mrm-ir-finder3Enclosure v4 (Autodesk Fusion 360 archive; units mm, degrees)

design "mrm-ir-finder3Enclosure" references "mrm-ir-finder3"
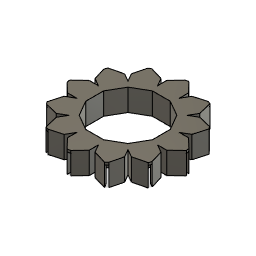
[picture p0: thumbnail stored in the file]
component_insert "Component Insert" AlongDistance 1.5 TaperAngle 0 TranslateX 0 TranslateY 0.5 TranslateZ 0 DistanceX 5.1838 DistanceY 5.3824 DistanceZ -1.6 OffsetDistanceX 0 OffsetDistanceY 0 countU 12 TotalAngle 360 AlongDistance 1.5 TaperAngle 0 TranslateX 0 TranslateY -0.5 TranslateZ 0 DistanceX 7.2 DistanceY 5.3 DistanceZ -1.5 OffsetDistanceX 0 OffsetDistanceY 0 TotalAngle 360 distance -0.2 distance -0.2 DistanceX 4.2933 DistanceY 6.2 DistanceZ -1.5 OffsetDistanceX 0 OffsetDistanceY 0 AlongDistance 0.5 TaperAngle 0 AlongDistance 0.5 TaperAngle 0 AlongDistance 0.5 TaperAngle 0 countU 12 TotalAngle 360 AlongDistance -0.5 TaperAngle 0 distance -0.2 AlongDistance -0.5 TaperAngle 0 AlongDistance -0.5 TaperAngle 0 AlongDistance -0.5 TaperAngle 0 AlongDistance -0.5 TaperAngle 0 AlongDistance -0.5 TaperAngle 0 AlongDistance -0.5 TaperAngle 0 DistanceX 1.5893 DistanceY 9.4 DistanceZ -0.4 OffsetDistanceX 0 OffsetDistanceY 0 AlongDistance -0.5 TaperAngle 0 AlongDistance -0.5 TaperAngle 0 AlongDistance -0.5 TaperAngle 0 AlongDistance -0.5 TaperAngle 0 AlongDistance -0.5 TaperAngle 0 AlongDistance -0.5 TaperAngle 0 AlongDistance -0.5 TaperAngle 0 AlongDistance -0.5 TaperAngle 0
sketch "Sketch8" plane through (0, 29.6609, 0) normal (0, 1, 0) x axis (-1, 0, 0)
  line L1 (-5.3393, 2.2304) -> (-2.6607, 2.2304)
  line L2 (-5.3393, -2.2518) -> (-5.3393, 2.2304)
  line L3 (-2.6607, -2.2518) -> (-5.3393, -2.2518)
  line L4 (-2.6607, 2.2304) -> (-2.6607, -2.2518)
  line L5 (-5.3411, 2.4304) -> (-2.6589, 2.4304)
  line L6 (-5.3393, -2.2518) -> (-2.6607, -2.2518)
  line L7 (-2.6589, -2.4518) -> (-5.3411, -2.4518)
  line L8 (-2.6, 1.9893) -> (-2.6, -2.0107)
  line L9 (-2.6607, 2.2304) -> (-5.3393, 2.2304)
  line L10 (-5.3411, 2.4304) -> (-2.6589, 2.4304)
  line L11 (-2.6589, 2.4304) -> (-5.3411, 2.4304)
  line L12 (-2.6589, -2.4518) -> (-2.6589, 2.4304)
  line L13 (-5.3411, -2.4518) -> (-2.6589, -2.4518)
  line L14 (-5.3411, 2.4304) -> (-5.3411, -2.4518)
  line L15 (-6.3411, -3.4518) -> (-1.6589, -3.4518)
  line L16 (-6.3411, 3.4304) -> (-6.3411, -3.4518)
  line L17 (-1.6589, 3.4304) -> (-6.3411, 3.4304)
  line L18 (-1.6589, -3.4518) -> (-1.6589, 3.4304)
  line L19 (-7.3411, -4.4518) -> (-0.6589, -4.4518)
  line L20 (-7.3411, 4.4304) -> (-7.3411, -4.4518)
  line L21 (-0.6589, 4.4304) -> (-7.3411, 4.4304)
  line L22 (-0.6589, -4.4518) -> (-0.6589, 4.4304)
  line L23 (-6.3411, 3.4304) -> (-1.6589, 3.4304)
  line L24 (-6.3411, 3.4304) -> (-6.3411, -3.4518)
  line L25 (-1.6589, -3.4518) -> (-6.3411, -3.4518)
  line L26 (-1.6589, -3.4518) -> (-1.6589, -2.9518)
  line L27 (-1.6589, 2.9304) -> (-1.6589, 3.4304)
  line L28 (-0.6589, 2.9304) -> (-1.6589, 2.9304)
  line L29 (-0.6589, 4.4304) -> (-0.6589, 2.9304)
  line L30 (-7.3411, 4.4304) -> (-0.6589, 4.4304)
  line L31 (-7.3411, -4.4518) -> (-7.3411, 4.4304)
  line L32 (-0.6589, -4.4518) -> (-7.3411, -4.4518)
  line L33 (-0.6589, -4.4518) -> (-0.6589, -2.9518)
  line L34 (-1.6589, -2.9518) -> (-0.6589, -2.9518)
  line L35 (2.1576, -0.0107) -> (-0.6589, 2.9304)
  line L36 (-0.6589, -2.9518) -> (2.1576, -0.0107)
  line L37 (3.9785, -0.0107) -> (-0.6589, 4.4304)
  line L38 (-0.6589, -4.4518) -> (3.9785, -0.0107)
  line L39 (-0.1379, 0.7317) -> (3, 0.7317)
  line L40 (-0.1379, -0.5) -> (3, -0.5)
  line L41 (3.2033, 0.7317) -> (-0.6589, 4.4304)
  line L42 (3.2033, 0.7317) -> (-0.6589, 4.4304)
  line L43 (1.4467, 0.7317) -> (3.2033, 0.7317)
  line L44 (-0.6589, 2.9304) -> (1.4467, 0.7317)
  line L45 (1.6891, -0.5) -> (-0.6589, -2.9518)
  line L46 (3.4676, -0.5) -> (1.6891, -0.5)
  line L47 (-0.6589, -4.4518) -> (3.4676, -0.5)
  closed curve K1 centre (-2.6589, -2.2518)
  closed curve K2 centre (-5.3411, -2.2518)
  arc A1 centre (-2.6, -0.0107) radius 2 clockwise from (-2.6, 1.9893) to (-2.6, -2.0107)
  closed curve K3 centre (-5.3411, 2.2304)
  closed curve K4 centre (-2.6589, 2.2304)
  point P9 (-2.6589, -2.4518)
  point P25 (-2.6589, -2.4518)
  point P7 (-5.3411, 2.4304)
  point P23 (-5.3411, 2.4304)
  point P35 (-1.6589, -2.9518)
  point P36 (-1.6589, 2.9304)
  point P37 (-0.6589, 2.9304)
  point P38 (-0.6589, -2.9518)
  point P45 (3.2033, 0.7317)
  point P46 (1.4467, 0.7317)
  point P47 (1.6891, -0.5)
  point P48 (3.4676, -0.5)
  point P30 (-1.6589, 3.4304)
  point P27 (-1.6589, -3.4518)
  horizontal L11
  vertical L12
  horizontal L13
  vertical L14
  coincident P9 P25
  coincident P7 P23
  coincident L18 P35
  coincident L18 P36
  coincident L22 P37
  perpendicular L22 L28
  coincident L22 P38
  perpendicular L32 L33
  perpendicular L18 L34
  perpendicular L36 L37
  horizontal L39
  horizontal L40
  coincident L37 P45
  coincident L39 P45
  coincident L35 P46
  coincident L39 P46
  coincident L36 P47
  coincident L40 P47
  coincident L40 P48
  coincident L38 P48
  dimension "d76" = -1
  dimension "d77" = -2
  dimension "d78" distance P30 P36 = 0.5
  dimension "d79" distance P27 P35 = 0.5
extrude "Extrude21" new body sketch "Sketch8" profile of L23 L24 L25 L26 L27 L28 L29 L30 L31 L32 L33 L34 L42 L43 L44 L45 L46 L47 along normal blind 1 and against normal blind 7
sketch "Sketch9" plane through (0, 30.6609, 0) normal (0, 1, 0) x axis (-1, 0, 0)
  line L1 (-1.6589, -2.9518) -> (-0.6589, -2.9518)
  line L2 (-1.6589, -3.4518) -> (-1.6589, -2.9518)
  line L3 (-6.3411, -3.4518) -> (-1.6589, -3.4518)
  line L4 (-6.3411, 3.4304) -> (-6.3411, -3.4518)
  line L5 (-1.6589, 3.4304) -> (-6.3411, 3.4304)
  line L6 (-1.6589, 2.9304) -> (-1.6589, 3.4304)
  line L7 (-0.6589, 2.9304) -> (-1.6589, 2.9304)
  line L8 (1.4467, 0.7317) -> (-0.6589, 2.9304)
  line L9 (3.2033, 0.7317) -> (1.4467, 0.7317)
  line L10 (-0.6589, 4.4304) -> (3.2033, 0.7317)
  line L11 (-7.3411, 4.4304) -> (-0.6589, 4.4304)
  line L12 (-7.3411, -4.4518) -> (-7.3411, 4.4304)
  line L13 (-0.6589, -4.4518) -> (-7.3411, -4.4518)
  line L14 (3.4676, -0.5) -> (-0.6589, -4.4518)
  line L15 (1.6891, -0.5) -> (3.4676, -0.5)
  line L16 (-0.6589, -2.9518) -> (1.6891, -0.5)
  line L17 (-0.6589, 4.4304) -> (-7.3411, 4.4304)
  line L18 (3.4676, -0.5) -> (3.2033, 0.7317)
  line L19 (-7.3411, -4.4518) -> (-0.6589, -4.4518)
  point P13 (-7.3411, 4.4304)
  point P18 (-7.3411, 4.4304)
  point P12 (-0.6589, 4.4304)
  point P19 (-0.6589, 4.4304)
  point P11 (3.2033, 0.7317)
  point P20 (3.2033, 0.7317)
  point P16 (3.4676, -0.5)
  point P21 (3.4676, -0.5)
  point P15 (-0.6589, -4.4518)
  point P22 (-0.6589, -4.4518)
  point P14 (-7.3411, -4.4518)
  point P23 (-7.3411, -4.4518)
  coincident P13 P18
  coincident P12 P19
  coincident P11 P20
  coincident P16 P21
  coincident P15 P22
  coincident P14 P23
extrude "Extrude22" add sketch "Sketch9" along normal blind 1
circular_pattern "C-Pattern4" countU 12 TotalAngle 360
combine "Combine4"

design "mrm-ir-finder3"
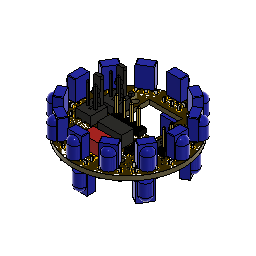
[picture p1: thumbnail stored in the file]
sketch "Outline" plane through (0, 0, 0) normal (0, 0, 1) x axis (1, 0, 0)
  line L1 (28, 23) -> (15, 23)
  line L2 (28, 29) -> (28, 23)
  line L3 (27, 29) -> (28, 29)
  line L4 (26.7, 30) -> (27, 29)
  line L5 (26.7, 34) -> (26.7, 30)
  line L6 (15.3, 34) -> (26.7, 34)
  line L7 (15.3, 30) -> (15.3, 34)
  line L8 (15, 29) -> (15.3, 30)
  line L9 (15, 23) -> (15, 29)
  circle C1 centre (21, 21) radius 19
  circle C2 centre (13.5, 31) radius 1
  circle C3 centre (28.5, 31) radius 1
  circle C4 centre (28.5, 11) radius 1
extrude "Extrude1" sketch "Outline" blind 1.5 bodies "Board"
canvas "Canvas1" bodies "Board"
canvas "Canvas2" bodies "Board"
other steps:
base_feature "Base Feature1"
base_feature "Base Feature1"
base_feature "Base Feature1"
base_feature "Base Feature1"
box_primitive "BoxPrimitive1" DistanceX 12.8016 DistanceY 2.6416 DistanceZ 0.1 OffsetDistanceX 0 OffsetDistanceY 0
base_feature "Base Feature1"
base_feature "Base Feature1"
base_feature "Base Feature1"
base_feature "Base Feature1"
base_feature "Base Feature1"
pcbextrude "PCBExtrude1"
base_feature "Base Feature1"
base_feature "Base Feature1"
box_primitive "BoxPrimitive1" DistanceX 3.2 DistanceY 2.5 DistanceZ 0.6 OffsetDistanceX 0 OffsetDistanceY 0
box_primitive "BoxPrimitive1" DistanceX 1 DistanceY 1 DistanceZ 1 OffsetDistanceX 0 OffsetDistanceY 0
box_primitive "BoxPrimitive1" DistanceX 8.25 DistanceY 4.25 DistanceZ 4.05 OffsetDistanceX 0 OffsetDistanceY 0
base_feature "Base Feature1"
base_feature "Base Feature1"
base_feature "Base Feature1"
base_feature "Base Feature1"
base_feature "Base Feature1"
base_feature "Base Feature1"
create_component "CreateComponent1"
create_component "CreateComponent1"
create_component "CreateComponent2"
create_component "CreateComponent4"
create_component "CreateComponent5"
create_component "CreateComponent6"
create_component "CreateComponent7"
create_component "CreateComponent9"
create_component "CreateComponent10"
create_component "CreateComponent12"
create_component "CreateComponent13"
create_component "CreateComponent14"
create_component "CreateComponent15"
create_component "CreateComponent1"
create_component "CreateComponent2"
as_built_joint "As-built1"
create_component "CreateComponent16"
create_component "CreateComponent17"
create_component "CreateComponent18"
create_component "CreateComponent1"
create_component "CreateComponent2"
create_component "CreateComponent3"
create_component "CreateComponent4"
named bodies: "Board"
